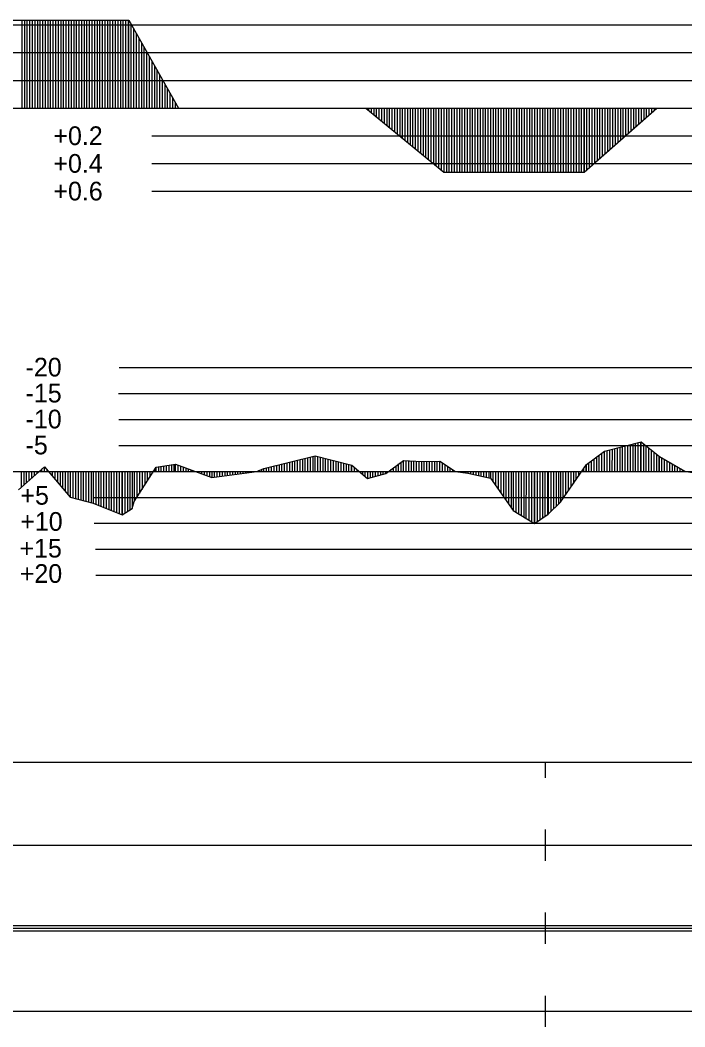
# Model space of a CAD drawing. Extents: x 2 to 10148, y 0 to 380.
# Drawn here: x 3249.3 to 3313.4, y 188.5 to 285.5 of the extents above; entities that cross this region are included whole.
import ezdxf

# ---------------------------------------------------------------- set-up
doc = ezdxf.new("R2010")
doc.units = 0
for name, color, linetype in [('POSUN_CARA', 7, 'Continuous'), ('POSUN_RASTR', 7, 'Continuous'), ('POSUN_TEXT', 7, 'Continuous'), ('RYCHL_RASTR', 7, 'Continuous'), ('ZRYCHL_CARA', 7, 'Continuous'), ('ZRYCHL_RASTR', 7, 'Continuous'), ('ZRYCHL_TEXT', 7, 'Continuous')]:
    doc.layers.add(name, color=color, linetype=linetype)

msp = doc.modelspace()

# ---------------------------------------------------------------- linework, layer by layer
at = {"layer": 'POSUN_CARA'}
for p, q in [((3305.61, 243.937), (3309.137, 244.843)), ((3307.353, 242), (3307.353, 244.385)), ((3307.603, 242), (3307.602, 244.449)), ((3307.853, 242), (3307.853, 244.513)), ((3308.103, 242), (3308.103, 244.577)), ((3308.353, 242), (3308.353, 244.641)), ((3308.603, 242), (3308.603, 244.706)), ((3308.853, 242), (3308.853, 244.77)), ((3309.103, 242), (3309.102, 244.834)), ((3309.137, 244.843), (3310.893, 243.446)), ((3309.137, 242), (3309.137, 244.843)), ((3309.387, 242), (3309.387, 244.644)), ((3309.637, 242), (3309.637, 244.445)), ((3272.775, 242.282), (3277.735, 243.516)), ((3277.275, 242), (3277.275, 243.402)), ((3277.525, 242), (3277.525, 243.464)), ((3277.735, 243.516), (3281.273, 242.602)), ((3277.735, 242), (3277.735, 243.516)), ((3277.985, 242), (3277.985, 243.451)), ((3278.235, 242), (3278.235, 243.387)), ((3303.858, 242.657), (3305.61, 243.937)), ((3304.858, 242), (3304.858, 243.388)), ((3305.108, 242), (3305.108, 243.571)), ((3305.358, 242), (3305.358, 243.753)), ((3305.608, 242), (3305.608, 243.936)), ((3305.61, 242), (3305.61, 243.937)), ((3305.86, 242), (3305.86, 244.001)), ((3306.11, 242), (3306.109, 244.065)), ((3306.36, 242), (3306.361, 244.13)), ((3306.61, 242), (3306.61, 244.194)), ((3306.86, 242), (3306.861, 244.258)), ((3307.11, 242), (3307.107, 244.322)), ((3309.887, 242), (3309.887, 244.246)), ((3310.137, 242), (3310.137, 244.047)), ((3310.387, 242), (3310.387, 243.848)), ((3310.637, 242), (3310.637, 243.649)), ((3310.887, 242), (3310.887, 243.45)), ((3310.893, 243.446), (3313.342, 242.016)), ((3310.893, 242), (3310.893, 243.446)), ((3249.141, 240.224), (3251.637, 242.454)), ((3251.637, 242.454), (3254.131, 239.529)), ((3251.637, 242), (3251.637, 242.454)), ((3262.399, 242.398), (3264.28, 242.709)), ((3262.649, 242), (3262.649, 242.439)), ((3262.899, 242), (3262.899, 242.481)), ((3263.149, 242), (3263.149, 242.522)), ((3263.399, 242), (3263.399, 242.563)), ((3263.649, 242), (3263.649, 242.604)), ((3263.899, 242), (3263.899, 242.646)), ((3264.149, 242), (3264.149, 242.687)), ((3264.28, 242.709), (3267.756, 241.403)), ((3264.28, 242), (3264.28, 242.709)), ((3264.53, 242), (3264.53, 242.615)), ((3264.78, 242), (3264.78, 242.521)), ((3265.03, 242), (3265.03, 242.427)), ((3273.525, 242), (3273.525, 242.469)), ((3273.775, 242), (3273.775, 242.531)), ((3274.025, 242), (3274.025, 242.593)), ((3274.275, 242), (3274.275, 242.655)), ((3274.525, 242), (3274.525, 242.717)), ((3274.775, 242), (3274.775, 242.78)), ((3275.025, 242), (3275.025, 242.842)), ((3275.275, 242), (3275.275, 242.904)), ((3275.525, 242), (3275.525, 242.966)), ((3275.775, 242), (3275.775, 243.028)), ((3276.025, 242), (3276.025, 243.091)), ((3276.275, 242), (3276.275, 243.153)), ((3276.525, 242), (3276.525, 243.215)), ((3276.775, 242), (3276.775, 243.277)), ((3277.025, 242), (3277.025, 243.339)), ((3278.485, 242), (3278.485, 243.322)), ((3278.735, 242), (3278.735, 243.258)), ((3278.985, 242), (3278.985, 243.193)), ((3279.235, 242), (3279.235, 243.128)), ((3279.485, 242), (3279.485, 243.064)), ((3279.735, 242), (3279.735, 242.999)), ((3279.985, 242), (3279.985, 242.935)), ((3280.235, 242), (3280.235, 242.87)), ((3280.485, 242), (3280.485, 242.805)), ((3280.735, 242), (3280.735, 242.741)), ((3280.985, 242), (3280.985, 242.676)), ((3281.235, 242), (3281.235, 242.611)), ((3281.273, 242.602), (3282.76, 241.311)), ((3281.273, 242), (3281.273, 242.602)), ((3284.519, 241.811), (3286.245, 243.062)), ((3285.519, 242), (3285.519, 242.536)), ((3285.769, 242), (3285.769, 242.717)), ((3286.019, 242), (3286.019, 242.899)), ((3286.245, 243.062), (3287.994, 242.962)), ((3286.245, 242), (3286.245, 243.062)), ((3286.495, 242), (3286.495, 243.048)), ((3286.745, 242), (3286.745, 243.034)), ((3286.995, 242), (3286.995, 243.019)), ((3287.245, 242), (3287.245, 243.005)), ((3287.495, 242), (3287.495, 242.991)), ((3287.745, 242), (3287.745, 242.976)), ((3287.994, 242.962), (3289.748, 242.973)), ((3287.994, 242), (3287.994, 242.962)), ((3288.244, 242), (3288.244, 242.964)), ((3288.494, 242), (3288.494, 242.965)), ((3288.744, 242), (3288.744, 242.967)), ((3288.994, 242), (3288.994, 242.968)), ((3289.244, 242), (3289.244, 242.97)), ((3289.494, 242), (3289.494, 242.971)), ((3289.744, 242), (3289.744, 242.973)), ((3289.748, 242.973), (3291.255, 242)), ((3289.748, 242), (3289.748, 242.973)), ((3289.998, 242), (3289.998, 242.811)), ((3290.248, 242), (3290.248, 242.65)), ((3290.498, 242), (3290.498, 242.489)), ((3301.355, 239.044), (3303.858, 242.657)), ((3303.855, 242), (3303.855, 242.653)), ((3303.858, 242), (3303.858, 242.657)), ((3304.108, 242), (3304.108, 242.84)), ((3304.358, 242), (3304.358, 243.023)), ((3304.608, 242), (3304.608, 243.205)), ((3311.143, 242), (3311.143, 243.3)), ((3311.393, 242), (3311.393, 243.154)), ((3311.643, 242), (3311.643, 243.008)), ((3311.893, 242), (3311.893, 242.862)), ((3312.143, 242), (3312.143, 242.716)), ((3312.393, 242), (3312.393, 242.57)), ((3312.643, 242), (3312.643, 242.424)), ((3249.391, 242), (3249.391, 240.447)), ((3249.641, 242), (3249.641, 240.671)), ((3249.891, 242), (3249.891, 240.894)), ((3250.141, 242), (3250.141, 241.117)), ((3250.391, 242), (3250.391, 241.341)), ((3250.641, 242), (3250.641, 241.564)), ((3250.891, 242), (3250.891, 241.787)), ((3251.141, 242), (3251.141, 242.011)), ((3251.391, 242), (3251.391, 242.234)), ((3251.887, 242), (3251.887, 242.16)), ((3252.137, 242), (3252.137, 241.867)), ((3252.387, 242), (3252.387, 241.574)), ((3252.637, 242), (3252.637, 241.281)), ((3252.887, 242), (3252.887, 240.987)), ((3253.137, 242), (3253.137, 240.694)), ((3253.387, 242), (3253.387, 240.401)), ((3253.637, 242), (3253.637, 240.108)), ((3253.887, 242), (3253.887, 239.814)), ((3254.131, 242), (3254.131, 239.529)), ((3254.381, 242), (3254.381, 239.464)), ((3254.631, 242), (3254.631, 239.399)), ((3254.881, 242), (3254.881, 239.334)), ((3255.131, 242), (3255.131, 239.269)), ((3255.381, 242), (3255.381, 239.203)), ((3255.631, 242), (3255.631, 239.138)), ((3255.881, 242), (3255.881, 239.073)), ((3256.131, 242), (3256.131, 239.008)), ((3256.331, 242), (3256.331, 238.956)), ((3256.581, 242), (3256.581, 238.853)), ((3256.831, 242), (3256.831, 238.751)), ((3257.081, 242), (3257.081, 238.648)), ((3257.331, 242), (3257.331, 238.546)), ((3257.581, 242), (3257.581, 238.443)), ((3257.831, 242), (3257.831, 238.341)), ((3258.081, 242), (3258.081, 238.239)), ((3258.331, 242), (3258.331, 238.136)), ((3258.581, 242), (3258.581, 238.034)), ((3258.831, 242), (3258.831, 237.931)), ((3259.081, 242), (3259.081, 237.829)), ((3259.129, 242), (3259.129, 237.809)), ((3259.379, 242), (3259.379, 237.966)), ((3259.629, 242), (3259.629, 238.123)), ((3259.879, 242), (3259.879, 238.279)), ((3260.094, 242), (3260.094, 238.414)), ((3260.296, 239.094), (3262.399, 242.398)), ((3260.296, 242), (3260.296, 239.094)), ((3260.546, 242), (3260.546, 239.487)), ((3260.796, 242), (3260.796, 239.88)), ((3261.046, 242), (3261.046, 240.273)), ((3261.296, 242), (3261.296, 240.665)), ((3261.546, 242), (3261.546, 241.058)), ((3261.796, 242), (3261.796, 241.451)), ((3262.046, 242), (3262.046, 241.843)), ((3262.296, 242), (3262.296, 242.236)), ((3262.399, 242), (3262.399, 242.398)), ((3265.28, 242), (3265.28, 242.333)), ((3265.53, 242), (3265.53, 242.239)), ((3265.78, 242), (3265.78, 242.145)), ((3266.03, 242), (3266.03, 242.051)), ((3266.28, 242), (3266.28, 241.957)), ((3266.53, 242), (3266.53, 241.863)), ((3266.78, 242), (3266.78, 241.769)), ((3267.03, 242), (3267.03, 241.675)), ((3267.28, 242), (3267.28, 241.581)), ((3267.53, 242), (3267.53, 241.487)), ((3267.756, 241.403), (3272.088, 242.002)), ((3267.756, 242), (3267.756, 241.403)), ((3268.006, 242), (3268.006, 241.437)), ((3268.256, 242), (3268.256, 241.472)), ((3268.506, 242), (3268.506, 241.506)), ((3268.756, 242), (3268.756, 241.541)), ((3269.006, 242), (3269.006, 241.576)), ((3269.256, 242), (3269.256, 241.61)), ((3269.506, 242), (3269.506, 241.645)), ((3269.756, 242), (3269.756, 241.679)), ((3270.006, 242), (3270.006, 241.714)), ((3270.256, 242), (3270.256, 241.749)), ((3270.506, 242), (3270.506, 241.783)), ((3270.756, 242), (3270.756, 241.818)), ((3271.006, 242), (3271.006, 241.852)), ((3271.256, 242), (3271.256, 241.887)), ((3271.506, 242), (3271.506, 241.922)), ((3271.756, 242), (3271.756, 241.956)), ((3272.006, 242), (3272.006, 241.991)), ((3272.088, 242.002), (3272.775, 242.282)), ((3272.088, 242), (3272.088, 242.002)), ((3272.338, 242), (3272.338, 242.104)), ((3272.588, 242), (3272.588, 242.206)), ((3272.775, 242), (3272.775, 242.282)), ((3273.025, 242), (3273.025, 242.344)), ((3273.275, 242), (3273.275, 242.406)), ((3281.523, 242), (3281.523, 242.385)), ((3281.773, 242), (3281.773, 242.167)), ((3282.023, 242), (3282.023, 241.95)), ((3282.273, 242), (3282.273, 241.733)), ((3282.523, 242), (3282.523, 241.516)), ((3282.76, 242), (3282.76, 241.311)), ((3282.76, 241.311), (3284.519, 241.811)), ((3283.01, 242), (3283.01, 241.382)), ((3283.26, 242), (3283.26, 241.453)), ((3283.51, 242), (3283.51, 241.524)), ((3283.76, 242), (3283.76, 241.595)), ((3284.01, 242), (3284.01, 241.666)), ((3284.26, 242), (3284.26, 241.737)), ((3284.51, 242), (3284.51, 241.808)), ((3284.519, 242), (3284.519, 241.811)), ((3284.769, 242), (3284.769, 241.992)), ((3285.019, 242), (3285.019, 242.173)), ((3285.269, 242), (3285.269, 242.355)), ((3290.748, 242), (3290.748, 242.327)), ((3290.998, 242), (3290.998, 242.166)), ((3291.248, 242), (3291.248, 242.005)), ((3291.255, 242), (3292.452, 241.824)), ((3291.255, 242), (3291.255, 242)), ((3291.505, 242), (3291.505, 241.963)), ((3291.755, 242), (3291.755, 241.926)), ((3292.005, 242), (3292.005, 241.889)), ((3292.255, 242), (3292.255, 241.853)), ((3292.452, 242), (3292.452, 241.824)), ((3292.452, 241.824), (3294.608, 241.355)), ((3292.702, 242), (3292.702, 241.769)), ((3292.952, 242), (3292.952, 241.715)), ((3293.202, 242), (3293.202, 241.661)), ((3293.452, 242), (3293.452, 241.606)), ((3293.702, 242), (3293.702, 241.552)), ((3293.952, 242), (3293.952, 241.497)), ((3294.202, 242), (3294.202, 241.443)), ((3294.452, 242), (3294.452, 241.389)), ((3294.608, 242), (3294.608, 241.355)), ((3294.858, 242), (3294.858, 241)), ((3295.108, 242), (3295.108, 240.646)), ((3295.358, 242), (3295.358, 240.291)), ((3295.608, 242), (3295.608, 239.937)), ((3295.858, 242), (3295.858, 239.582)), ((3296.108, 242), (3296.108, 239.227)), ((3296.358, 242), (3296.358, 238.873)), ((3296.608, 242), (3296.608, 238.518)), ((3296.817, 242), (3296.817, 238.222)), ((3297.067, 242), (3297.068, 238.069)), ((3297.317, 242), (3297.317, 237.917)), ((3297.567, 242), (3297.568, 237.764)), ((3297.817, 242), (3297.817, 237.612)), ((3298.073, 237.456), (3298.074, 242)), ((3298.318, 242), (3298.318, 237.307)), ((3298.568, 242), (3298.568, 237.154)), ((3298.818, 242), (3298.818, 237.002)), ((3298.867, 242), (3298.867, 236.972)), ((3299.117, 242), (3299.117, 237.146)), ((3299.367, 242), (3299.367, 237.321)), ((3299.617, 242), (3299.617, 237.496)), ((3299.867, 242), (3299.867, 237.67)), ((3300.117, 242), (3300.117, 237.845)), ((3300.188, 242), (3300.188, 237.895)), ((3300.438, 242), (3300.438, 238.141)), ((3300.688, 242), (3300.688, 238.387)), ((3300.938, 242), (3300.938, 238.634)), ((3301.188, 242), (3301.188, 238.88)), ((3301.355, 242), (3301.355, 239.044)), ((3301.605, 242), (3301.605, 239.405)), ((3301.855, 242), (3301.855, 239.766)), ((3302.105, 242), (3302.105, 240.127)), ((3302.355, 242), (3302.355, 240.488)), ((3302.605, 242), (3302.605, 240.849)), ((3302.855, 242), (3302.855, 241.21)), ((3303.105, 242), (3303.105, 241.571)), ((3303.355, 242), (3303.355, 241.932)), ((3303.605, 242), (3303.605, 242.292)), ((3312.893, 242), (3312.893, 242.278)), ((3313.143, 242), (3313.143, 242.132)), ((3313.342, 242.016), (3315.169, 241.717)), ((3313.342, 242), (3313.342, 242.016)), ((3294.608, 241.355), (3296.817, 238.222)), ((3254.131, 239.529), (3256.331, 238.956)), ((3256.331, 238.956), (3259.129, 237.809)), ((3260.094, 238.414), (3260.296, 239.094)), ((3300.188, 237.895), (3301.355, 239.044)), ((3259.129, 237.809), (3260.094, 238.414)), ((3296.817, 238.222), (3298.867, 236.972)), ((3298.867, 236.972), (3300.188, 237.895))]:
    msp.add_line(p, q, dxfattribs=at)
at = {"layer": 'POSUN_RASTR'}
for p, q in [((3258.848, 252), (3470.165, 252)), ((3258.76, 249.5), (3470.119, 249.5)), ((3258.804, 247), (3470.119, 247)), ((3258.804, 244.5), (3470.303, 244.5)), ((3155.54, 242), (4045.764, 242)), ((3256.338, 239.5), (3458, 239.5)), ((3256.443, 237), (3458, 237)), ((3256.549, 234.5), (3458, 234.5)), ((3256.579, 232), (3458, 232))]:
    msp.add_line(p, q, dxfattribs=at)
at = {"layer": 'RYCHL_RASTR'}
for p, q in [((3155.54, 214), (4046.979, 214)), ((3299.908, 212.5), (3299.908, 214)), ((3299.908, 204.5), (3299.908, 207.5)), ((3155.54, 206), (4046.951, 206)), ((3299.908, 196.5), (3299.908, 199.5)), ((3155.54, 198.25), (4046.943, 198.25)), ((3155.54, 198), (4046.933, 198)), ((3155.54, 197.75), (4046.924, 197.75)), ((3299.908, 188.5), (3299.908, 191.5)), ((3155.54, 190), (4046.935, 190))]:
    msp.add_line(p, q, dxfattribs=at)
at = {"layer": 'ZRYCHL_CARA'}
for p, q in [((3221.486, 285.466), (3259.759, 285.466)), ((3249.486, 277), (3249.486, 285.466)), ((3249.736, 277), (3249.736, 285.466)), ((3249.986, 277), (3249.986, 285.466)), ((3250.236, 277), (3250.236, 285.466)), ((3250.486, 277), (3250.486, 285.466)), ((3250.736, 277), (3250.736, 285.466)), ((3250.986, 277), (3250.986, 285.466)), ((3251.236, 277), (3251.236, 285.466)), ((3251.486, 277), (3251.486, 285.466)), ((3251.736, 277), (3251.736, 285.466)), ((3251.986, 277), (3251.986, 285.466)), ((3252.236, 277), (3252.236, 285.466)), ((3252.486, 277), (3252.486, 285.466)), ((3252.736, 277), (3252.736, 285.466)), ((3252.986, 277), (3252.986, 285.466)), ((3253.236, 277), (3253.236, 285.466)), ((3253.486, 277), (3253.486, 285.466)), ((3253.736, 277), (3253.736, 285.466)), ((3253.986, 277), (3253.986, 285.466)), ((3254.236, 277), (3254.236, 285.466)), ((3254.486, 277), (3254.486, 285.466)), ((3254.736, 277), (3254.736, 285.466)), ((3254.986, 277), (3254.986, 285.466)), ((3255.236, 277), (3255.236, 285.466)), ((3255.486, 277), (3255.486, 285.466)), ((3255.736, 277), (3255.736, 285.466)), ((3255.986, 277), (3255.986, 285.466)), ((3256.236, 277), (3256.236, 285.466)), ((3256.486, 277), (3256.486, 285.466)), ((3256.736, 277), (3256.736, 285.466)), ((3256.986, 277), (3256.986, 285.466)), ((3257.236, 277), (3257.236, 285.466)), ((3257.486, 277), (3257.486, 285.466)), ((3257.736, 277), (3257.736, 285.466)), ((3257.986, 277), (3257.986, 285.466)), ((3258.236, 277), (3258.236, 285.466)), ((3258.486, 277), (3258.486, 285.466)), ((3258.736, 277), (3258.736, 285.466)), ((3258.986, 277), (3258.986, 285.466)), ((3259.236, 277), (3259.236, 285.466)), ((3259.486, 277), (3259.486, 285.466)), ((3259.736, 277), (3259.736, 285.466)), ((3259.759, 277), (3259.759, 285.466)), ((3259.759, 285.466), (3264.559, 277)), ((3260.009, 277), (3260.009, 285.025)), ((3260.259, 277), (3260.259, 284.584)), ((3260.509, 277), (3260.509, 284.143)), ((3260.759, 277), (3260.759, 283.702)), ((3261.009, 277), (3261.009, 283.261)), ((3261.259, 277), (3261.259, 282.82)), ((3261.509, 277), (3261.509, 282.379)), ((3261.759, 277), (3261.759, 281.939)), ((3262.009, 277), (3262.009, 281.498)), ((3262.259, 277), (3262.259, 281.057)), ((3262.509, 277), (3262.509, 280.616)), ((3262.759, 277), (3262.759, 280.175)), ((3263.009, 277), (3263.009, 279.734)), ((3263.259, 277), (3263.259, 279.293)), ((3263.509, 277), (3263.509, 278.852)), ((3263.759, 277), (3263.759, 278.411)), ((3264.009, 277), (3264.009, 277.97)), ((3264.259, 277), (3264.259, 277.529)), ((3155.54, 277), (4045.764, 277)), ((3264.509, 277), (3264.509, 277.088)), ((3282.618, 277), (3290.118, 270.835)), ((3282.868, 277), (3282.868, 276.794)), ((3283.118, 277), (3283.118, 276.589)), ((3283.368, 277), (3283.368, 276.383)), ((3283.618, 277), (3283.618, 276.178)), ((3283.868, 277), (3283.868, 275.972)), ((3284.118, 277), (3284.118, 275.767)), ((3284.368, 277), (3284.368, 275.561)), ((3284.618, 277), (3284.618, 275.356)), ((3284.868, 277), (3284.868, 275.15)), ((3285.118, 277), (3285.118, 274.945)), ((3285.368, 277), (3285.368, 274.739)), ((3285.618, 277), (3285.618, 274.534)), ((3285.868, 277), (3285.868, 274.328)), ((3286.118, 277), (3286.118, 274.123)), ((3286.368, 277), (3286.368, 273.917)), ((3286.618, 277), (3286.618, 273.712)), ((3286.868, 277), (3286.868, 273.506)), ((3287.118, 277), (3287.118, 273.301)), ((3287.368, 277), (3287.368, 273.095)), ((3287.618, 277), (3287.618, 272.89)), ((3287.868, 277), (3287.868, 272.684)), ((3288.118, 277), (3288.118, 272.479)), ((3288.368, 277), (3288.368, 272.273)), ((3288.618, 277), (3288.618, 272.068)), ((3288.868, 277), (3288.868, 271.862)), ((3289.118, 277), (3289.118, 271.657)), ((3289.368, 277), (3289.368, 271.451)), ((3289.618, 277), (3289.618, 271.246)), ((3289.868, 277), (3289.868, 271.04)), ((3290.118, 277), (3290.118, 270.835)), ((3290.368, 277), (3290.368, 270.835)), ((3290.618, 277), (3290.618, 270.835)), ((3290.868, 277), (3290.868, 270.835)), ((3291.118, 277), (3291.118, 270.835)), ((3291.368, 277), (3291.368, 270.835)), ((3291.618, 277), (3291.618, 270.835)), ((3291.868, 277), (3291.868, 270.835)), ((3292.118, 277), (3292.118, 270.835)), ((3292.368, 277), (3292.368, 270.835)), ((3292.618, 277), (3292.618, 270.835)), ((3292.868, 277), (3292.868, 270.835)), ((3293.118, 277), (3293.118, 270.835)), ((3293.368, 277), (3293.368, 270.835)), ((3293.618, 277), (3293.618, 270.835)), ((3293.868, 277), (3293.868, 270.835)), ((3294.118, 277), (3294.118, 270.835)), ((3294.368, 277), (3294.368, 270.835)), ((3294.618, 277), (3294.618, 270.835)), ((3294.868, 277), (3294.868, 270.835)), ((3295.118, 277), (3295.118, 270.835)), ((3295.368, 277), (3295.368, 270.835)), ((3295.618, 277), (3295.618, 270.835)), ((3295.868, 277), (3295.868, 270.835)), ((3296.118, 277), (3296.118, 270.835)), ((3296.368, 277), (3296.368, 270.835)), ((3296.618, 277), (3296.618, 270.835)), ((3296.868, 277), (3296.868, 270.835)), ((3297.118, 277), (3297.118, 270.835)), ((3297.368, 277), (3297.368, 270.835)), ((3297.618, 277), (3297.618, 270.835)), ((3297.868, 277), (3297.868, 270.835)), ((3298.118, 277), (3298.118, 270.835)), ((3298.368, 277), (3298.368, 270.835)), ((3298.618, 277), (3298.618, 270.835)), ((3298.868, 277), (3298.868, 270.835)), ((3299.118, 277), (3299.118, 270.835)), ((3299.368, 277), (3299.368, 270.835)), ((3299.618, 277), (3299.618, 270.835)), ((3299.868, 277), (3299.868, 270.835)), ((3300.118, 277), (3300.118, 270.835)), ((3300.368, 277), (3300.368, 270.835)), ((3300.618, 277), (3300.618, 270.835)), ((3300.868, 277), (3300.868, 270.835)), ((3301.118, 277), (3301.118, 270.835)), ((3301.368, 277), (3301.368, 270.835)), ((3301.618, 277), (3301.618, 270.835)), ((3301.868, 277), (3301.868, 270.835)), ((3302.118, 277), (3302.118, 270.835)), ((3302.368, 277), (3302.368, 270.835)), ((3302.618, 277), (3302.618, 270.835)), ((3302.868, 277), (3302.868, 270.835)), ((3303.118, 277), (3303.118, 270.835)), ((3303.368, 277), (3303.368, 270.835)), ((3303.618, 277), (3303.618, 270.835)), ((3303.635, 277), (3303.635, 270.835)), ((3303.635, 270.835), (3310.635, 277)), ((3303.885, 277), (3303.885, 271.055)), ((3304.135, 277), (3304.135, 271.275)), ((3304.385, 277), (3304.385, 271.495)), ((3304.635, 277), (3304.635, 271.715)), ((3304.885, 277), (3304.885, 271.936)), ((3305.135, 277), (3305.135, 272.156)), ((3305.385, 277), (3305.385, 272.376)), ((3305.635, 277), (3305.635, 272.596)), ((3305.885, 277), (3305.885, 272.816)), ((3306.135, 277), (3306.135, 273.036)), ((3306.385, 277), (3306.385, 273.257)), ((3306.635, 277), (3306.635, 273.477)), ((3306.885, 277), (3306.885, 273.697)), ((3307.135, 277), (3307.135, 273.917)), ((3307.385, 277), (3307.385, 274.137)), ((3307.635, 277), (3307.635, 274.358)), ((3307.885, 277), (3307.885, 274.578)), ((3308.135, 277), (3308.135, 274.798)), ((3308.385, 277), (3308.385, 275.018)), ((3308.635, 277), (3308.635, 275.238)), ((3308.885, 277), (3308.885, 275.459)), ((3309.135, 277), (3309.135, 275.679)), ((3309.385, 277), (3309.385, 275.899)), ((3309.635, 277), (3309.635, 276.119)), ((3309.885, 277), (3309.885, 276.339)), ((3310.135, 277), (3310.135, 276.56)), ((3310.385, 277), (3310.385, 276.78)), ((3290.118, 270.835), (3303.635, 270.835))]:
    msp.add_line(p, q, dxfattribs=at)
at = {"layer": 'ZRYCHL_RASTR'}
for p, q in [((3043.293, 285), (3262, 285)), ((3262, 285), (3458, 285)), ((3043.313, 282.333), (3262, 282.333)), ((3262, 282.333), (3458, 282.333)), ((3043.292, 279.667), (3262, 279.667)), ((3262, 279.667), (3458, 279.667)), ((3262, 274.333), (3458, 274.333)), ((3262, 271.667), (3458, 271.667)), ((3262, 269), (3458, 269))]:
    msp.add_line(p, q, dxfattribs=at)

# ---------------------------------------------------------------- texts
at = {"layer": 'POSUN_TEXT'}
for s, p in [('-20', (3249.82, 251.144)), ('-15', (3249.82, 248.644)), ('-10', (3249.82, 246.144)), ('-5', (3249.82, 243.644)), ('+5', (3249.324, 238.796)), ('+10', (3249.309, 236.281)), ('+15', (3249.234, 233.705)), ('+20', (3249.264, 231.266))]:
    msp.add_text(s, height=1.8, dxfattribs=at).set_placement(p)
at = {"layer": 'ZRYCHL_TEXT'}
for s, p in [('+0.2', (3252.5, 273.433)), ('+0.4', (3252.5, 270.767)), ('+0.6', (3252.5, 268.1))]:
    msp.add_text(s, height=1.8, dxfattribs=at).set_placement(p)

doc.saveas('drawing.dxf')
